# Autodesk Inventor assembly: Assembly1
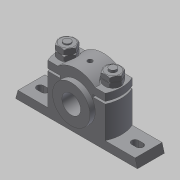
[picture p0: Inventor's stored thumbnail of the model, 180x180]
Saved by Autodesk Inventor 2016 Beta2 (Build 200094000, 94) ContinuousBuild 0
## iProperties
Created: 2015-03
Part Number: Assembly1
Document SubType Name: Assembly
Designer: Sandeep
Author: Sandeep
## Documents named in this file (7)
- C:\Autodesk Inventor 2016\c09\tut 02\Plumber Block\Assembly1.iam
- C:\Autodesk Inventor 2016\c09\tut 02\Plumber Block\Casting.ipt
- C:\Autodesk Inventor 2016\c09\tut 02\Plumber Block\Brasses.ipt
- C:\Autodesk Inventor 2016\c09\tut 02\Plumber Block\Cap.ipt
- C:\Autodesk Inventor 2016\c09\tut 02\Plumber Block\Bolt.ipt
- C:\Autodesk Inventor 2016\c09\tut 02\Plumber Block\Nut.ipt
- C:\Autodesk Inventor 2016\c09\tut 02\Plumber Block\Lock Nut.ipt
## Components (9 placed, 6 different names)
1. Casting:1 — Mate:1, Mate:2, Insert:1, Insert:2, Angle:1, Angle:2
2. Brasses:1 — Mate:1, Mate:2, Mate:3, Mate:4
3. Cap:1 — Mate:3, Mate:4, Insert:3, Insert:5
4. Bolt:1 — Insert:1, Angle:2
5. Bolt:2 — Insert:2, Angle:1, Mate:5
6. Nut:1 — Insert:5
7. Nut:2 — Insert:3, Insert:4
8. Lock Nut:1 — Insert:4
9. Lock Nut:2 — Mate:5
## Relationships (12: Mate 5, Insert 5, Angle 2)
- Mate:1: Casting:1 ↔ Brasses:1
- Mate:2: Casting:1 ↔ Brasses:1
- Mate:3: Brasses:1 ↔ Cap:1
- Mate:4: Brasses:1 ↔ Cap:1
- Insert:1: Casting:1 ↔ Bolt:1
- Insert:2: Casting:1 ↔ Bolt:2
- Angle:1: Casting:1 ↔ Bolt:2
- Angle:2: Casting:1 ↔ Bolt:1
- Insert:3: Cap:1 ↔ Nut:2
- Insert:4: Nut:2 ↔ Lock Nut:1
- Insert:5: Cap:1 ↔ Nut:1
- Mate:5: Bolt:2 ↔ Lock Nut:2
